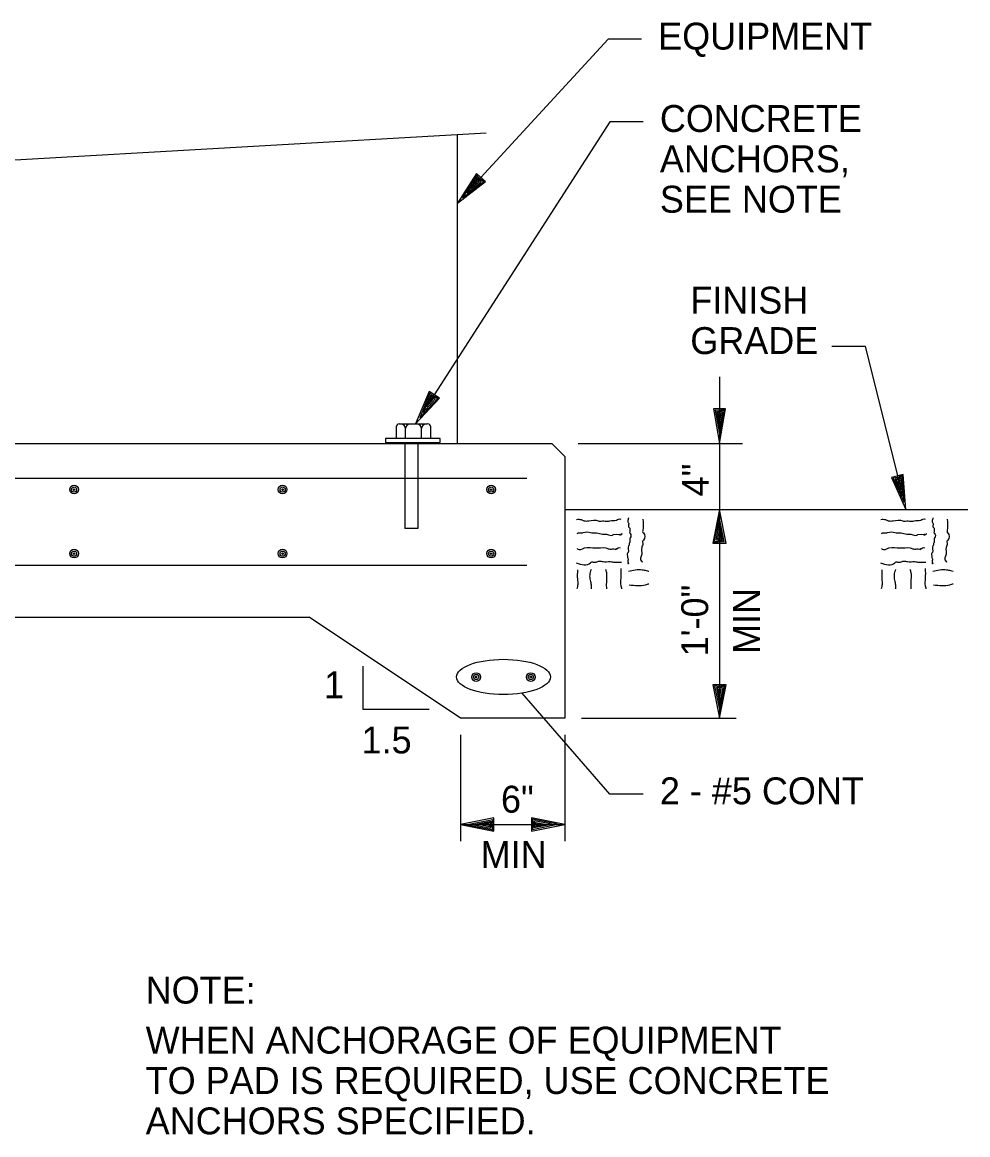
# Model space of a CAD drawing. Extents: x -121875 to -117742, y -103854 to -101122.
# Drawn here: x -121635 to -121424.2, y -102466.2 to -102218.2 of the extents above; entities that cross this region are included whole.
import ezdxf

# ---------------------------------------------------------------- set-up
doc = ezdxf.new("R2010")
doc.units = 0
for name, color, linetype in [('G-MARK', 7, 'Continuous'), ('G-TEXT', 7, 'Continuous'), ('Misc CnstDet(22)', 7, 'Continuous'), ('S-FNDN-PILE', 7, 'Continuous')]:
    doc.layers.add(name, color=color, linetype=linetype)

# ---------------------------------------------------------------- blocks, each defined once
blk = doc.blocks.new('ARROW')
at = {"layer": 'S-FNDN-PILE'}
blk.add_lwpolyline([(-0.002083, 0.000367), (-0.002083, -0.000367), (0, 0), (-0.002083, 0.000367), (-0.001983, 0), (-0.002017, -0.000267), (-0.00045, 0.000017), (-0.002017, 0.0003), (-0.001917, 0), (-0.001917, -0.000167), (-0.000833, 0.000017), (-0.001883, 0.0002), (-0.001867, -0.000117), (-0.001217, 0), (-0.001817, 0.0001), (-0.001767, -0.00005), (-0.00155, 0), (-0.002083, 0)], dxfattribs=at)

msp = doc.modelspace()

# ---------------------------------------------------------------- linework, layer by layer
at = {"layer": 'G-MARK'}
for p, q in [((-121479.55, -102297.28), (-121479.55, -102326.86)), ((-121479.55, -102298.58), (-121479.55, -102312.1)), ((-121511.05, -102312.1), (-121474.38, -102312.1)), ((-121479.55, -102326.86), (-121479.55, -102373.35)), ((-121510.32, -102373.35), (-121475.83, -102373.35)), ((-121537.29, -102397.06), (-121514.04, -102397.06))]:
    msp.add_line(p, q, dxfattribs=at)
for points in [[(-121496.93, -102222.01), (-121504.37, -102222.01), (-121532.73, -102252.81)], [(-121496.54, -102240.38), (-121503.98, -102240.38), (-121543.14, -102301.24)], [(-121454.49, -102290.45), (-121447.05, -102290.45), (-121439.89, -102319.33)], [(-121438.57, -102319), (-121441.21, -102319.66), (-121438.03, -102326.86), (-121438.57, -102319), (-121439.8, -102319.69), (-121440.79, -102319.81), (-121438.37, -102325.22), (-121438.75, -102319.3), (-121439.74, -102319.93), (-121440.34, -102320.08), (-121438.71, -102323.83), (-121438.99, -102319.88), (-121440.12, -102320.22), (-121439.12, -102322.46), (-121439.29, -102320.21), (-121439.79, -102320.52), (-121439.41, -102321.26), (-121439.89, -102319.33)], [(-121544.3, -102371.42), (-121558.97, -102371.42), (-121558.97, -102361.72)], [(-121496.54, -102390.27), (-121503.98, -102390.27), (-121523.53, -102367.75)]]:
    msp.add_lwpolyline(points, dxfattribs=at)
msp.add_ellipse((-121527.7, -102364.15), major_axis=(-10.49, 0), ratio=0.373805, dxfattribs=at)
at = {"layer": 'G-TEXT'}
for points in [[(-121531.72, -102253.74), (-121533.73, -102251.89), (-121537.98, -102258.52), (-121531.72, -102253.74), (-121532.98, -102253.09), (-121533.62, -102252.33), (-121536.8, -102257.33), (-121532.07, -102253.75), (-121533.15, -102253.27), (-121533.6, -102252.85), (-121535.83, -102256.28), (-121532.68, -102253.87), (-121533.59, -102253.11), (-121534.91, -102255.19), (-121533.12, -102253.8), (-121533.66, -102253.56), (-121534.07, -102254.27), (-121532.73, -102252.81)], [(-121541.99, -102301.98), (-121544.28, -102300.5), (-121547.33, -102307.76), (-121541.99, -102301.98), (-121543.34, -102301.55), (-121544.11, -102300.91), (-121546.37, -102306.38), (-121542.33, -102302.05), (-121543.47, -102301.76), (-121543.99, -102301.42), (-121545.6, -102305.18), (-121542.91, -102302.27), (-121543.94, -102301.68), (-121544.88, -102303.95), (-121543.36, -102302.27), (-121543.93, -102302.13), (-121544.21, -102302.91), (-121543.14, -102301.24)], [(-121478.19, -102304.41), (-121480.91, -102304.41), (-121479.55, -102312.1), (-121478.19, -102304.41), (-121479.55, -102304.78), (-121480.54, -102304.66), (-121479.49, -102310.36), (-121478.43, -102304.66), (-121479.55, -102305.03), (-121480.17, -102305.03), (-121479.49, -102309), (-121478.81, -102305.15), (-121479.98, -102305.21), (-121479.55, -102307.57), (-121479.18, -102305.4), (-121479.74, -102305.59), (-121479.55, -102306.33), (-121479.55, -102304.41)], [(-121478.07, -102365.91), (-121481.04, -102365.91), (-121479.56, -102373.35), (-121478.07, -102365.91), (-121479.56, -102366.27), (-121480.64, -102366.15), (-121479.49, -102371.74), (-121478.34, -102366.15), (-121479.56, -102366.5), (-121480.23, -102366.5), (-121479.49, -102370.37), (-121478.74, -102366.62), (-121480.03, -102366.68), (-121479.56, -102369), (-121479.15, -102366.86), (-121479.76, -102367.04), (-121479.56, -102367.81), (-121479.56, -102365.91)], [(-121529.86, -102398.56), (-121529.86, -102395.58), (-121537.3, -102397.07), (-121529.86, -102398.56), (-121530.21, -102397.07), (-121530.09, -102395.99), (-121535.69, -102397.13), (-121530.09, -102398.28), (-121530.45, -102397.07), (-121530.45, -102396.39), (-121534.32, -102397.13), (-121530.57, -102397.88), (-121530.63, -102396.59), (-121532.95, -102397.07), (-121530.81, -102397.47), (-121530.99, -102396.86), (-121531.76, -102397.07), (-121529.86, -102397.07)], [(-121521.49, -102395.58), (-121521.49, -102398.56), (-121514.05, -102397.07), (-121521.49, -102395.58), (-121521.13, -102397.07), (-121521.25, -102398.15), (-121515.66, -102397), (-121521.25, -102395.85), (-121520.9, -102397.07), (-121520.9, -102397.74), (-121517.03, -102397), (-121520.78, -102396.26), (-121520.72, -102397.54), (-121518.4, -102397.07), (-121520.54, -102396.66), (-121520.36, -102397.27), (-121519.59, -102397.07), (-121521.49, -102397.07)]]:
    msp.add_lwpolyline(points, dxfattribs=at)
at = {"layer": 'Misc CnstDet(22)'}
for p, q in [((-121644.26, -102249.28), (-121531.59, -102242.89)), ((-121537.98, -102312.1), (-121537.98, -102243.27)), ((-121551.56, -102310.86), (-121551.56, -102308.38)), ((-121550.94, -102307.76), (-121544.61, -102307.76)), ((-121549.57, -102310.86), (-121549.57, -102308.75)), ((-121545.98, -102310.86), (-121545.98, -102308.75)), ((-121543.87, -102310.86), (-121543.87, -102308.38)), ((-121777.16, -102312.1), (-121516.95, -102312.1)), ((-121549.66, -102311.91), (-121549.66, -102331.1)), ((-121546.76, -102311.91), (-121546.76, -102331.1)), ((-121516.95, -102312.1), (-121514.04, -102315)), ((-121514.04, -102315), (-121514.04, -102373.35)), ((-121771.63, -102319.85), (-121522.48, -102319.85)), ((-121514.04, -102326.86), (-121424.19, -102326.86)), ((-121546.76, -102331.1), (-121549.66, -102331.1)), ((-121771.63, -102339.22), (-121522.48, -102339.22)), ((-121723.06, -102350.84), (-121571.05, -102350.84)), ((-121537.29, -102373.35), (-121571.05, -102350.84)), ((-121514.04, -102373.35), (-121537.29, -102373.35)), ((-121537.29, -102377.07), (-121537.29, -102400.79)), ((-121514.04, -102377.07), (-121514.04, -102400.79))]:
    msp.add_line(p, q, dxfattribs=at)
msp.add_lwpolyline([(-121553.98, -102311.91), (-121541.82, -102311.91), (-121541.82, -102310.98), (-121553.98, -102310.98)], close=True, dxfattribs=at)
for centre, radius in [((-121623.44, -102322.39), 0.969), ((-121623.44, -102322.39), 0.581), ((-121576.94, -102322.39), 0.969), ((-121576.94, -102322.39), 0.581), ((-121530.45, -102322.39), 0.969), ((-121530.45, -102322.39), 0.581), ((-121623.44, -102322.39), 0.176), ((-121576.94, -102322.39), 0.176), ((-121530.45, -102322.39), 0.176), ((-121623.44, -102336.67), 0.969), ((-121623.44, -102336.67), 0.581), ((-121623.44, -102336.67), 0.176), ((-121576.94, -102336.67), 0.969), ((-121576.94, -102336.67), 0.581), ((-121576.94, -102336.67), 0.176), ((-121530.45, -102336.67), 0.969), ((-121530.45, -102336.67), 0.581), ((-121530.45, -102336.67), 0.176), ((-121533.81, -102364.18), 0.969), ((-121533.81, -102364.18), 0.581), ((-121533.81, -102364.18), 0.176), ((-121521.59, -102364.18), 0.969), ((-121521.59, -102364.18), 0.581), ((-121521.59, -102364.18), 0.176)]:
    msp.add_circle(centre, radius, dxfattribs=at)
for centre, radius, start, end in [((-121550.96, -102308.43), 0.674, 90, 180), ((-121550.56, -102308.8), 1.01, 360, 90), ((-121548.54, -102308.8), 1.01, 90, 180), ((-121546.99, -102308.8), 1.01, 360, 90), ((-121544.96, -102308.8), 1.01, 90, 180), ((-121544.56, -102308.43), 0.674, 0, 90)]:
    msp.add_arc(centre, radius, start, end, dxfattribs=at)
for points in [[(-121511.4, -102329.03), (-121510.41, -102329.09), (-121509.79, -102329.34), (-121508.67, -102329.34), (-121506.56, -102329.34), (-121506.19, -102329.46), (-121505.63, -102329.34), (-121504.39, -102329.46), (-121504.02, -102329.34), (-121502.53, -102329.21), (-121502.03, -102328.96), (-121501.54, -102328.96)], [(-121499.8, -102328.72), (-121499.93, -102329.09), (-121499.93, -102329.71), (-121499.8, -102329.83), (-121499.8, -102330.7), (-121499.68, -102330.82), (-121499.55, -102331.82), (-121499.55, -102332.06), (-121499.43, -102332.19), (-121499.43, -102333.18), (-121499.55, -102333.43), (-121499.55, -102334.17), (-121499.68, -102334.42), (-121499.68, -102334.79), (-121499.8, -102334.92), (-121499.93, -102336.4), (-121500.05, -102336.53), (-121500.05, -102337.46), (-121500.05, -102337.58), (-121499.93, -102337.83), (-121499.93, -102338.7), (-121499.8, -102338.95), (-121499.93, -102338.95), (-121499.93, -102338.82)], [(-121496.64, -102328.96), (-121496.64, -102331.57), (-121496.64, -102331.94), (-121496.51, -102332.06), (-121496.51, -102333.68), (-121496.64, -102333.8), (-121496.64, -102334.42), (-121496.89, -102335.29), (-121496.89, -102336.78), (-121496.89, -102338.45), (-121496.76, -102338.57), (-121496.89, -102338.57)], [(-121443.54, -102329.03), (-121442.55, -102329.09), (-121441.93, -102329.34), (-121440.81, -102329.34), (-121438.7, -102329.34), (-121438.33, -102329.46), (-121437.77, -102329.34), (-121436.53, -102329.46), (-121436.16, -102329.34), (-121434.67, -102329.21), (-121434.18, -102328.96), (-121433.68, -102328.96)], [(-121431.94, -102328.72), (-121432.07, -102329.09), (-121432.07, -102329.71), (-121431.94, -102329.83), (-121431.94, -102330.7), (-121431.82, -102330.82), (-121431.7, -102331.82), (-121431.7, -102332.06), (-121431.57, -102332.19), (-121431.57, -102333.18), (-121431.7, -102333.43), (-121431.7, -102334.17), (-121431.82, -102334.42), (-121431.82, -102334.79), (-121431.94, -102334.92), (-121432.07, -102336.4), (-121432.19, -102336.53), (-121432.19, -102337.46), (-121432.19, -102337.58), (-121432.07, -102337.83), (-121432.07, -102338.7), (-121431.94, -102338.95), (-121432.07, -102338.95), (-121432.07, -102338.82)], [(-121428.78, -102328.96), (-121428.78, -102331.57), (-121428.78, -102331.94), (-121428.66, -102332.06), (-121428.66, -102333.68), (-121428.78, -102333.8), (-121428.78, -102334.42), (-121429.03, -102335.29), (-121429.03, -102336.78), (-121429.03, -102338.45), (-121428.91, -102338.57), (-121429.03, -102338.57)], [(-121511.27, -102332.19), (-121511.03, -102332.06), (-121510.28, -102332.06), (-121509.91, -102331.94), (-121508.3, -102331.94), (-121507.68, -102332.06), (-121506.93, -102332.06), (-121505.63, -102332.31), (-121505.01, -102332.31), (-121504.02, -102332.56), (-121503.4, -102332.56), (-121503.15, -102332.44), (-121501.66, -102332.44), (-121501.79, -102332.44), (-121501.29, -102332.31), (-121501.29, -102332.19), (-121501.29, -102332.31)], [(-121443.41, -102332.19), (-121443.17, -102332.06), (-121442.42, -102332.06), (-121442.05, -102331.94), (-121440.44, -102331.94), (-121439.82, -102332.06), (-121439.07, -102332.06), (-121437.77, -102332.31), (-121437.15, -102332.31), (-121436.16, -102332.56), (-121435.54, -102332.56), (-121435.29, -102332.44), (-121433.8, -102332.44), (-121433.93, -102332.44), (-121433.43, -102332.31), (-121433.43, -102332.19), (-121433.43, -102332.31)], [(-121511.27, -102335.54), (-121511.15, -102335.66), (-121509.66, -102335.41), (-121507.18, -102335.41), (-121504.89, -102335.41), (-121503.89, -102335.66), (-121502.78, -102335.66), (-121502.53, -102335.66), (-121502.53, -102335.54), (-121502.53, -102335.66), (-121502.53, -102335.54), (-121502.28, -102335.54), (-121502.16, -102335.41), (-121501.66, -102335.41)], [(-121443.41, -102335.54), (-121443.29, -102335.66), (-121441.8, -102335.41), (-121439.32, -102335.41), (-121437.03, -102335.41), (-121436.04, -102335.66), (-121434.92, -102335.66), (-121434.67, -102335.66), (-121434.67, -102335.54), (-121434.67, -102335.66), (-121434.67, -102335.54), (-121434.42, -102335.54), (-121434.3, -102335.41), (-121433.8, -102335.41)], [(-121511.52, -102338.7), (-121508.3, -102338.7), (-121508.17, -102338.57), (-121507.55, -102338.57), (-121507.06, -102338.57), (-121506.31, -102338.33), (-121505.51, -102338.45), (-121503.89, -102338.45), (-121502.9, -102338.57), (-121501.41, -102338.57)], [(-121443.66, -102338.7), (-121440.44, -102338.7), (-121440.31, -102338.57), (-121439.69, -102338.57), (-121439.2, -102338.57), (-121438.45, -102338.33), (-121437.65, -102338.45), (-121436.04, -102338.45), (-121435.04, -102338.57), (-121433.56, -102338.57)], [(-121511.21, -102340.25), (-121511.21, -102342.36), (-121511.15, -102343.53), (-121511.34, -102344.53)], [(-121508.17, -102340.19), (-121508.48, -102341.36), (-121508.36, -102342.6), (-121508.17, -102343.66), (-121508.17, -102344.53)], [(-121504.95, -102340.12), (-121504.76, -102340.87), (-121504.76, -102343.1), (-121504.76, -102344.53)], [(-121501.54, -102340), (-121501.54, -102342.17), (-121501.54, -102343.84), (-121501.41, -102344.28), (-121501.41, -102344.53)], [(-121499.86, -102340.56), (-121496.76, -102340.25), (-121495.89, -102340.43), (-121495.34, -102340.56), (-121495.27, -102340.56)], [(-121443.35, -102340.25), (-121443.35, -102342.36), (-121443.29, -102343.53), (-121443.48, -102344.53)], [(-121440.31, -102340.19), (-121440.62, -102341.36), (-121440.5, -102342.6), (-121440.31, -102343.66), (-121440.31, -102344.53)], [(-121437.09, -102340.12), (-121436.9, -102340.87), (-121436.9, -102343.1), (-121436.9, -102344.53)], [(-121433.68, -102340), (-121433.68, -102342.17), (-121433.68, -102343.84), (-121433.56, -102344.28), (-121433.56, -102344.53)], [(-121432.01, -102340.56), (-121428.91, -102340.25), (-121428.04, -102340.43), (-121427.48, -102340.56), (-121427.42, -102340.56)], [(-121499.68, -102343.6), (-121496.02, -102343.6), (-121495.58, -102343.47), (-121495.27, -102343.41)], [(-121431.82, -102343.6), (-121428.16, -102343.6), (-121427.73, -102343.47), (-121427.42, -102343.41)]]:
    msp.add_spline(points, degree=3, dxfattribs=at)

# ---------------------------------------------------------------- block references
at = {"layer": 'G-TEXT', "xscale": 3571.703056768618, "yscale": 4058.0876675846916, "rotation": 90}
msp.add_blockref('ARROW', (-121479.56, -102326.86), dxfattribs=at)

# ---------------------------------------------------------------- texts
at = {"layer": 'G-MARK'}
for s, p in [('CONCRETE', (-121492.83, -102242.66)), ('ANCHORS,', (-121492.83, -102251.66)), ('SEE NOTE', (-121492.83, -102260.66)), ('FINISH', (-121486.05, -102283.18)), ('GRADE', (-121486.05, -102292.18)), ('2 - #5 CONT', (-121492.83, -102392.55))]:
    msp.add_text(s, height=6, dxfattribs=at).set_placement(p)
at = {"layer": 'Misc CnstDet(22)'}
for s, p in [('EQUIPMENT', (-121493.21, -102224.3)), ('1', (-121567.7, -102368.9)), ('1.5', (-121559.34, -102381.21)), ('6"', (-121528.26, -102394.41)), ('MIN', (-121532.79, -102406.76)), ('NOTE:', (-121607.47, -102436.97)), ('WHEN ANCHORAGE OF EQUIPMENT', (-121607.47, -102448.13)), ('TO PAD IS REQUIRED, USE CONCRETE', (-121607.47, -102457.13)), ('ANCHORS SPECIFIED.', (-121607.47, -102466.13))]:
    msp.add_text(s, height=6, dxfattribs=at).set_placement(p)
for s, p in [('4"', (-121481.92, -102323.9)), ('1\'-0"', (-121482.07, -102359.57)), ('MIN', (-121470.51, -102359.04))]:
    msp.add_text(s, height=6, rotation=90, dxfattribs=at).set_placement(p)

doc.saveas('drawing.dxf')
